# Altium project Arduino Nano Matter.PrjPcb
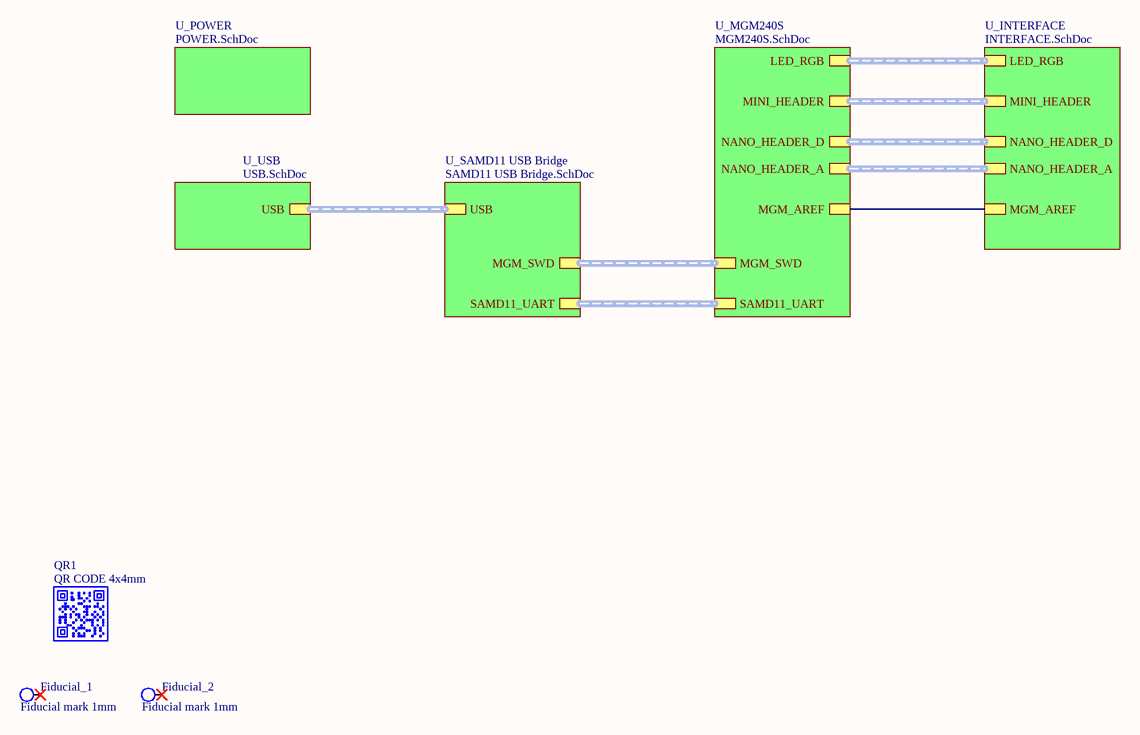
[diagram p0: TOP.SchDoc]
ASSEMBLY_BGA: _; ASSEMBLY_PRESSFIT: _; ASSEMBLY_SMD: X; ASSEMBLY_THT: X; BOARD_CODENAME: NANO MATTER; BOARD_INFO_AUTHOR_REV: Silvio Navaretti; BOARD_INFO_Er: _; BOARD_INFO_FLEX: _; BOARD_INFO_FR4: X; BOARD_INFO_FR4_HTG: _; BOARD_INFO_IPC1: _; BOARD_INFO_IPC2: X; BOARD_INFO_IPC3: _; BOARD_INFO_IPC_NA: _; BOARD_INFO_NUMBER_OF_LAYERS: 4; BOARD_INFO_PCB_SIZE: 43.18mm x 17.78mm; BOARD_INFO_POLYMIDE: _; BOARD_INFO_RIGID: X; BOARD_INFO_RIGID/FLEX: _; BOARD_INFO_TBD: _; BOARD_INFO_THICKNESS: 1.6mm; DRILLS_BLIND: _; DRILLS_BURIED: _; DRILLS_COPPER_FILLING: _; DRILLS_FULL: X; DRILLS_LASER: _; DRILLS_PRESSFIT: _; DRILLS_RESIN_FILLING: _; DRILLS_SLOT: _; DRILLS_SOLDER_FILLING: X; FINISH_ADJUSTMENTS: _; FINISH_EDGE_PLATING: _; FINISH_ENIG: X; FINISH_HAL: _; FINISH_HAL_LF: _; FINISH_NI/AU: _; FINISH_SILK_BOTTOM: X; FINISH_SILK_COLOR: WHITE; FINISH_SILK_TOP: X; FINISH_SN/PB: _; FINISH_SOLDERMASK_BOTTOM: X; FINISH_SOLDERMASK_COLOR: BLUE; FINISH_SOLDERMASK_PEELABLE_BOTTOM: _; FINISH_SOLDERMASK_PEELABLE_COLOR: _; FINISH_SOLDERMASK_PEELABLE_TOP: _; FINISH_SOLDERMASK_TOP: X; FINISH_TABS: _; FINISH_TBD: _; INSULATION_MIN_INNER: 0.127mm; INSULATION_MIN_OUTER: 0.127mm; PANEL_MILLING: X; PANEL_NOT_REQUESTED: _; PANEL_NUMBER_OF_FIGURES: 28; PANEL_PROVIDED: X; PANEL_REQUESTED: _; PANEL_SCORING: X; PANEL_SIZE: 211mm x 180.46mm; PANEL_TABS: _; SKU: ABX00112; TRACK_MIN_WIDTH_INNER: 0.127mm; TRACK_MIN_WIDTH_OUTER: 0.127mm; Version: V0.5; VIA_1: _; VIA_1_HOLE_MM: _; VIA_1_PAD_MM: _; VIA_2: _; VIA_2_HOLE_MM: _; VIA_2_PAD_MM: _; VIA_3: _; VIA_3_HOLE_MM: _; VIA_3_PAD_MM: _; VIA_4: _; VIA_4_HOLE_MM: _; VIA_4_PAD_MM: _; VIA_5: _; VIA_5_HOLE_MM: _; VIA_5_PAD_MM: _; VIA_THROUGH: X; VIA_THROUGH_HOLE_MM: 0.2; VIA_THROUGH_PAD_MM: 0.4
6 sheets, 72 parts. Net scope: hierarchical (ports join the sheet entries above them; power ports are global).
Board files: PCB.PcbDoc, PANEL.PcbDoc
Sheets:
  TOP.SchDoc
    U_SAMD11 USB Bridge = SAMD11 USB Bridge.SchDoc
    U_USB = USB.SchDoc
    U_POWER = POWER.SchDoc
    U_MGM240S = MGM240S.SchDoc
    U_INTERFACE = INTERFACE.SchDoc

## Sheet TOP.SchDoc: TOP
size A4; SheetNumber: 1; SheetTotal: 6

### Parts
Fiducial_1  Fiducial mark 1mm  [Fiducial mark 1mm-Footprint-1]  (no BOM)
Fiducial_2  Fiducial mark 1mm  [Fiducial mark 1mm-Footprint-1]  (no BOM)
QR1  QR CODE 4x4mm  [QR CODE 4x4mm]  (no BOM)

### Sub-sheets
U_INTERFACE = INTERFACE.SchDoc: LED_RGB (harness LED RGB), MINI_HEADER (harness 10P MINI HEADER), NANO_HEADER_D (harness NANO_HEADER_D), NANO_HEADER_A (harness NANO_HEADER_A), MGM_AREF
U_MGM240S = MGM240S.SchDoc: LED_RGB (harness LED RGB), MINI_HEADER (harness 10P MINI HEADER), NANO_HEADER_D (harness NANO_HEADER_D), NANO_HEADER_A (harness NANO_HEADER_A), MGM_SWD (harness UART), SAMD11_UART (harness UART), MGM_AREF
U_POWER = POWER.SchDoc: no entries
U_SAMD11 USB Bridge = SAMD11 USB Bridge.SchDoc: USB (harness USB), SAMD11_UART (harness SAMD11_UART), MGM_SWD (harness MGM_SW)
U_USB = USB.SchDoc: USB (harness USB)

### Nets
MGM_AREF: sheet U_MGM240S/MGM_AREF, sheet U_INTERFACE/MGM_AREF

Not connected (* = marked no-connect by the designer): Fiducial_1 1*; Fiducial_2 1*

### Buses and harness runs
harness sheet U_INTERFACE/LED_RGB = sheet U_MGM240S/LED_RGB
harness sheet U_INTERFACE/MINI_HEADER = sheet U_MGM240S/MINI_HEADER
harness sheet U_INTERFACE/NANO_HEADER_A = sheet U_MGM240S/NANO_HEADER_A
harness sheet U_INTERFACE/NANO_HEADER_D = sheet U_MGM240S/NANO_HEADER_D
harness sheet U_MGM240S/MGM_SWD = sheet U_SAMD11 USB Bridge/MGM_SWD
harness sheet U_MGM240S/SAMD11_UART = sheet U_SAMD11 USB Bridge/SAMD11_UART
harness sheet U_SAMD11 USB Bridge/USB = sheet U_USB/USB

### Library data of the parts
Fiducial_1 Fiducial_2 = UT0023-A.7: Fiducial mark 1mm clearance 2mm
QR1 = QR-0001-A.2: QR CODE 4x4mm on layer 34 (This is not a component); Code Arduino: QRCODE_4x4mm

## Sheet SAMD11 USB Bridge.SchDoc: SAMD11 BRIDGE
size A4; SheetNumber: 4; SheetTotal: 6
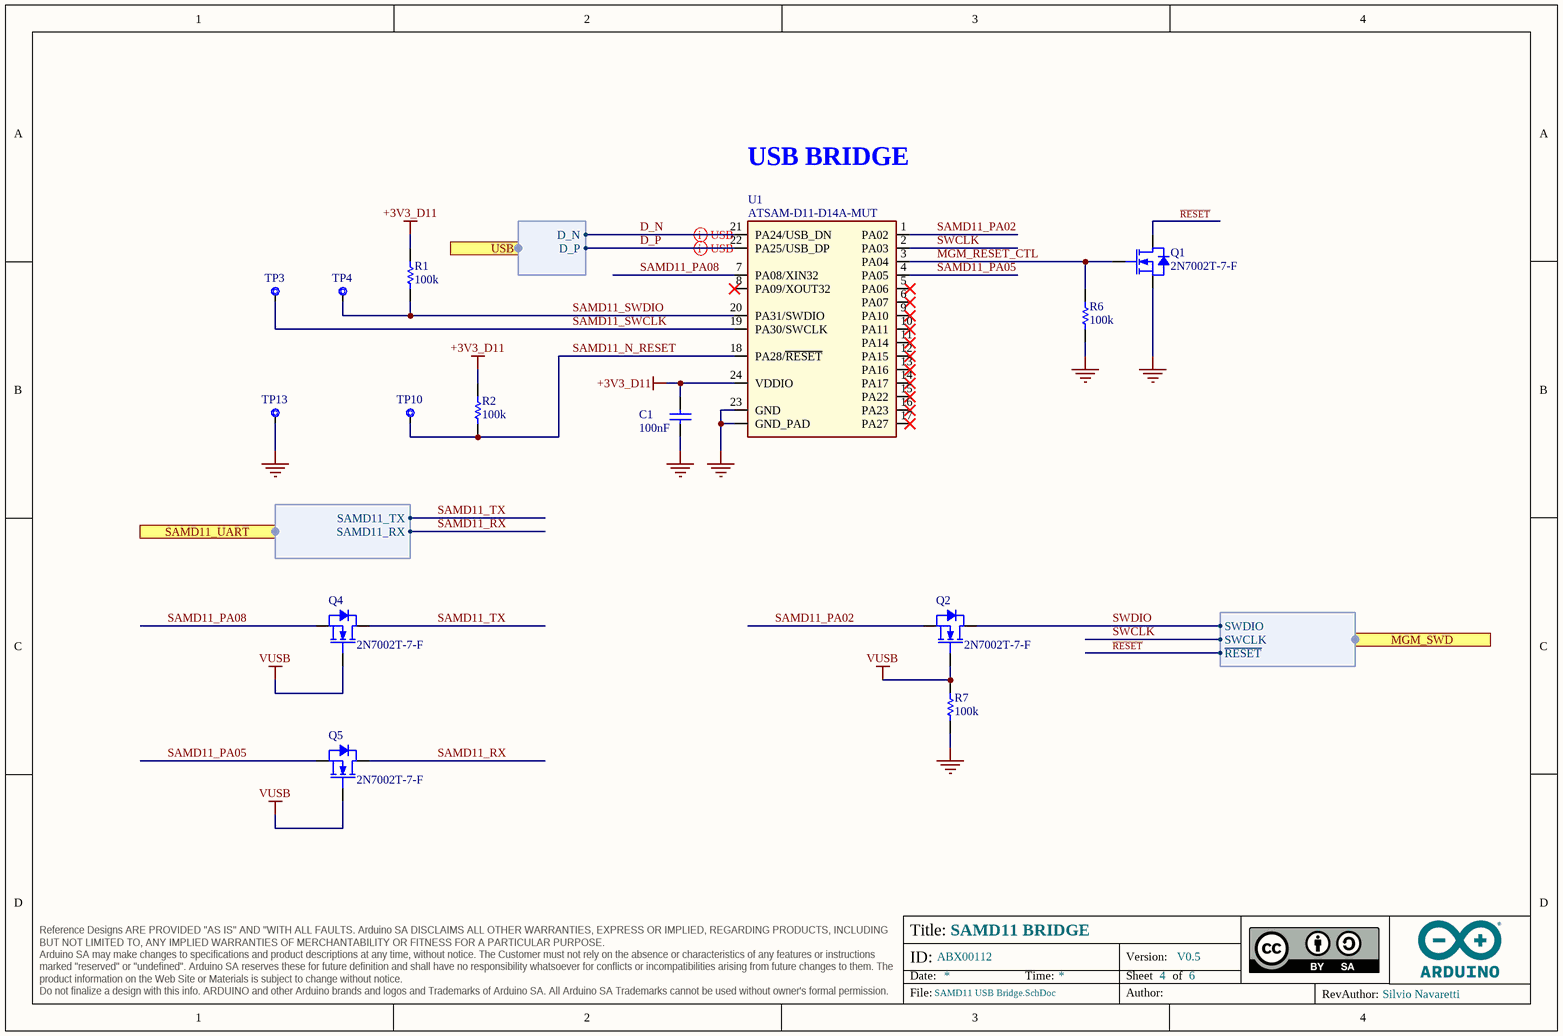
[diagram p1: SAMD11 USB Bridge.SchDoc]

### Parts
C1  value 100nF  [CAP-0201]  (hidden comment: CL03A104KP3NNNC)
Q1  2N7002T-7-F  [SOT523]
Q2  2N7002T-7-F  [SOT523]
Q4  2N7002T-7-F  [SOT523]
Q5  2N7002T-7-F  [SOT523]
R1  value 100k  [RES-0201]  (hidden comment: RC0201FR-07100KL)
R2  value 100k  [RES-0201]  (hidden comment: RC0201FR-07100KL)
R6  value 100k  [RES-0201]  (hidden comment: RC0201FR-07100KL)
R7  value 100k  [RES-0201]  (hidden comment: RC0201FR-07100KL)
TP3  Test point 1.00mm  [TP-1.00MM]  (value not drawn)  (no BOM)
TP4  Test point 1.00mm  [TP-1.00MM]  (value not drawn)  (no BOM)
TP10  Test point 1.00mm  [TP-1.00MM]  (value not drawn)  (no BOM)
TP13  Test point 1.00mm  [TP-1.00MM]  (value not drawn)  (no BOM)
U1  ATSAM-D11-D14A-MUT  [VQFN24]

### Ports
MGM_SWD (harness MGM_SWD), SAMD11_UART (harness SAMD11_UART), USB (out, harness USB)

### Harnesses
USB: D_P, D_N
SAMD11_UART: SAMD11_RX, SAMD11_TX
MGM_SWD: SWDIO, SWCLK, ~{RESET}

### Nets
+3V3_D11: C1.2 R1.2 R2.1 U1.24(VDDIO)
GND: C1.1 Q1.S R6.2 R7.2 TP13.X U1.23(GND) U1.EXP(GND_PAD)
VUSB: Q2.G Q4.G Q5.G R7.1
D_N: U1.21(PA24/USB_DN) ; port USB.D_N
D_P: U1.22(PA25/USB_DP) ; port USB.D_P
MGM_RESET_CTL: Q1.G R6.1 U1.3(PA04)  [project net MGM_RESET_CTL_4]
~{RESET}: Q1.D ; port MGM_SWD.~{RESET}
SAMD11_N_RESET: R2.2 TP10.X U1.18(PA28/~{RESET})  [project net SAMD11_N_RESET_4]
SAMD11_PA02: Q2.S U1.1(PA02)  [project net SAMD11_PA02_4]
SAMD11_PA05: Q5.S U1.4(PA05)  [project net SAMD11_PA05_4]
SAMD11_PA08: Q4.S U1.7(PA08/XIN32)  [project net SAMD11_PA08_4]
SAMD11_RX: Q5.D ; port SAMD11_UART.SAMD11_RX
SAMD11_SWCLK: TP3.X U1.19(PA30/SWCLK)  [project net SAMD11_SWCLK_4]
SAMD11_SWDIO: R1.1 TP4.X U1.20(PA31/SWDIO)  [project net SAMD11_SWDIO_4]
SAMD11_TX: Q4.D ; port SAMD11_UART.SAMD11_TX
SWCLK: U1.2(PA03) ; port MGM_SWD.SWCLK
SWDIO: Q2.D ; port MGM_SWD.SWDIO

Not connected (* = marked no-connect by the designer): U1 5(PA06)* 6(PA07)* 8(PA09/XOUT32)* 9(PA10)* 10(PA11)* 11(PA14)* 12(PA15)* 13(PA16)* 14(PA17)* 15(PA22)* 16(PA23)* 17(PA27)*

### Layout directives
differential pair; differential pair class USB: D_N, D_P

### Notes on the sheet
- USB BRIDGE

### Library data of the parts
C1 = C0113-A.6: CAP CHIP 0201 100nF 10% 10V X5R; Manufacturer: Samsung Electro-Mechanics; Code Arduino: C0113
Q1 Q2 Q4 Q5 = T0003-A.2: MOSFET N-CH 60V 115mA SOT523; Manufacturer: Diodes Inc.; Device Type: Mosfet N-CH SMD; Code Arduino: 2368
R1 R2 R6 R7 = R0146-A.21: RES CHIP 0201 100k 1% 1/20W; Manufacturer: Yageo; Power: 50mW; Code Arduino: R0146; Temperature coefficient: 200ppm
TP3 TP4 TP10 TP13 = UT0013-A.6: Manufacturer: This is not a component
U1 = U0040-A.9: IC uC Cortex M0, 16KB flash, 4KB SRAM, 48MHz, USB, 3x SERCOM, RTC, 12PWM, ADC 12b, DAC 10b, VDD 1.6V to 3.6V, QFN24 4x4mm; Manufacturer: Microchip

## Sheet USB.SchDoc: USB
size A4; SheetNumber: 3; SheetTotal: 6
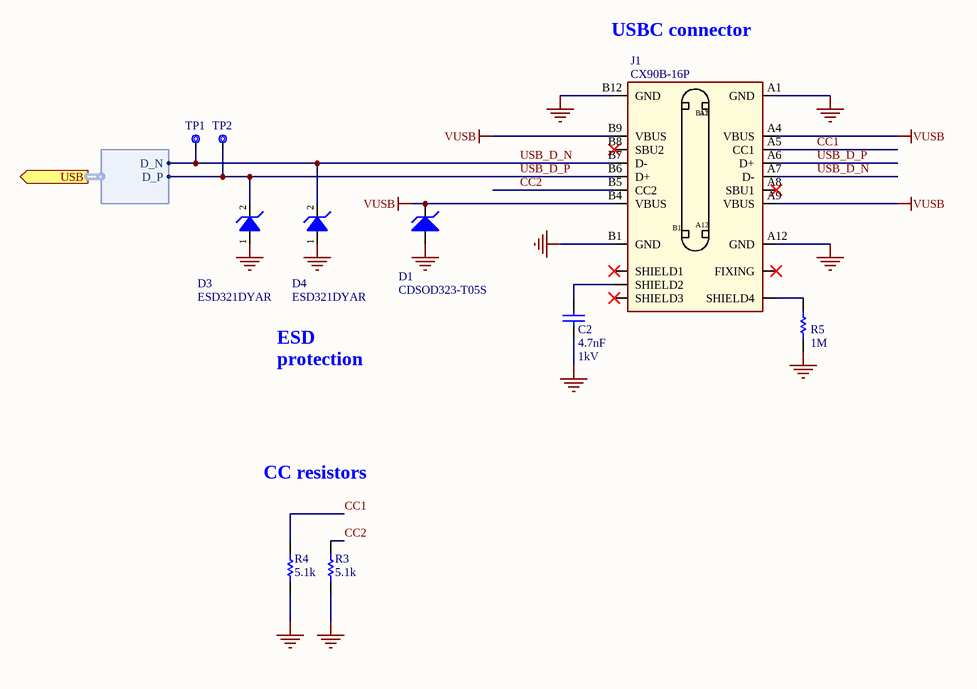
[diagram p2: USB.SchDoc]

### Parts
C2  value 4.7nF  Voltage: 1kV  [CAP-0805]  (hidden comment: FV21X472K102ECG)
D1  CDSOD323-T05S  [SOD323 CATHODE MARK]
D3  ESD321DYAR  [ESD321DYAR]
D4  ESD321DYAR  [ESD321DYAR]
J1  CX90B-16P  [CX90B-16P-Footprint-1]
R3  value 5.1k  [RES-0201]  (hidden comment: RC0201FR-075K1L)
R4  value 5.1k  [RES-0201]  (hidden comment: RC0201FR-075K1L)
R5  value 1M  [RES-0402]  (hidden comment: CRCW04021M00FKED)
TP1  Test point 1.00mm  [TP-1.00MM]  (value not drawn)  (no BOM)
TP2  Test point 1.00mm  [TP-1.00MM]  (value not drawn)  (no BOM)

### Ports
USB (out, harness USB)

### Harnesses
USB: D_P, D_N

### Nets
GND: C2.1 D1.2(A) D3.1 D4.1 J1.A1(GND) J1.A12(GND) J1.B1(GND) J1.B12(GND) R3.1 R4.1 R5.1
VUSB: D1.1(C) J1.A4(VBUS) J1.A9(VBUS) J1.B4(VBUS) J1.B9(VBUS)
CC1: J1.A5(CC1) R4.2  [project net CC1_3]
CC2: J1.B5(CC2) R3.2  [project net CC2_3]
USB_D_N: D4.2 J1.A7(D-) J1.B7(D-) TP1.X ; port USB.D_N  [project net D_N]
USB_D_P: D3.2 J1.A6(D+) J1.B6(D+) TP2.X ; port USB.D_P  [project net D_P]
NetC2_2: C2.2 J1.SHIELD2
NetJ1_SHIELD4: J1.SHIELD4 R5.2

Not connected (* = marked no-connect by the designer): J1 A8(SBU1)* B8(SBU2)* FIXING* SHIELD1* SHIELD3*

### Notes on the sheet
- USBC connector
- ESD
  protection
- CC resistors

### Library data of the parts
C2 = C0059-A.14: CAP CHIP 0805 4.7nF 10% 1000V X7R; Manufacturer: PSA Shenzen; Code Arduino: 0689
D1 = D0081-A.1: DIODE TVS Vr 5V, Vbr min 6V, 500W, SOD323; Manufacturer: Bourns; Direction: Unidirectional; Code Arduino: D0081
D3 D4 = P0022-4: TVS 1CH, 30kV, USB 2.0 ETH 10/100/1000, 0-3.6V, 0.9pF, IEC61000-4-5 peak current 80A surge 40W 6A, DC breakdown min 4.5V, SOD523 1.6x0.8mm; Manufacturer: Texas Instruments; Code Arduino: P0022
J1 = J0272-A.3: CONN RCPT USB3.1 TYPEC 16POS SMD; Manufacturer: Hirose; Code Arduino: J0272
R3 R4 = R0169-A.24: RES CHIP 0201 5.1k 1% 1/20W; Manufacturer: Yageo; Power: 50mW; Code Arduino: R0169; Temperature coefficient: 200ppm
R5 = R0058-A.24: RES CHIP 0402 1M 1% 1/16W; Manufacturer: Vishay; Power: 62.5mW; Code Arduino: 0139; Temperature coefficient: 100ppm
TP1 TP2 = UT0013-A.6: Manufacturer: This is not a component

## Sheet POWER.SchDoc: POWER
size A4; SheetNumber: 2; SheetTotal: 6
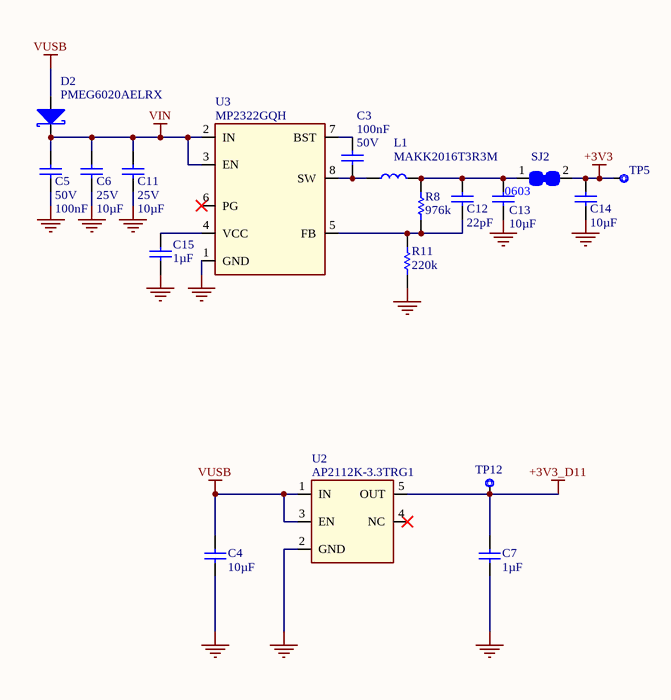
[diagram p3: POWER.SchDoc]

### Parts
C3  value 100nF  Voltage: 50V  [CAP-0402]  (hidden comment: GRM155R61H104KE19D)
C4  value 10µF  [CAP-0603]  (hidden comment: C1608A106M250NT)
C5  value 100nF  Voltage: 50V  [CAP-0402]  (hidden comment: GRM155R61H104KE19D)
C6  value 10µF  Voltage: 25V  [CAP-0603]  (hidden comment: C1608A106M250NT)
C7  value 1µF  [CAP-0201]  (hidden comment: GRM033R60J105MEA2D)
C11  value 10µF  Voltage: 25V  [CAP-0603]  (hidden comment: C1608A106M250NT)
C12  value 22pF  [CAP-0402]  (hidden comment: 0402N220J500CT)
C13  value 10µF  [CAP-0603]  (hidden comment: C1608A106M250NT)
C14  value 10µF  [CAP-0603]  (hidden comment: C1608A106M250NT)
C15  value 1µF  [CAP-0201]  (hidden comment: GRM033R60J105MEA2D)
D2  PMEG6020AELRX  [SOD123-1]
L1  MAKK2016T3R3M  [MAKK2016T3R3M-Footprint-1]
R8  value 976k  [RES-0201]  (hidden comment: RMCF0201FT976K)
R11  value 220k  [RES-0201]  (hidden comment: AC0201FR-07220KL)
SJ2  SOLDER JUMPER CLOSED 0603  [SJ 0603 CLOSED]  (value not drawn)  (no BOM)
TP5  Test point 1.00mm  [TP-1.00MM]  (value not drawn)  (no BOM)
TP12  Test point 1.00mm  [TP-1.00MM]  (value not drawn)  (no BOM)
U2  AP2112K-3.3TRG1  [SOT25]
U3  MP2322GQH  [QFN50P150X200X90-8L]

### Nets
+3V3: C14.2 SJ2.2 TP5.X
+3V3_D11: C7.2 TP12.X U2.5(OUT)
GND: C4.1 C5.2 C6.1 C7.1 C11.1 C13.1 C14.1 C15.1 R11.1 U2.2(GND) U3.1(GND)
VIN: C5.1 C6.2 C11.2 D2.C U3.2(IN) U3.3(EN)
VUSB: C4.2 D2.A U2.1(IN) U2.3(EN)
NetC3_1: C3.1 L1.1 U3.8(SW)
NetC3_2: C3.2 U3.7(BST)
NetC12_1: C12.1 R8.1 R11.2 U3.5(FB)
NetC12_2: C12.2 C13.2 L1.2 R8.2 SJ2.1
NetC15_2: C15.2 U3.4(VCC)

Not connected (* = marked no-connect by the designer): U2 4(NC)*; U3 6(PG)*

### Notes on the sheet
- BUCK 3V3
- LDO 3V3 DEDICATED TO D11

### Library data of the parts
C3 C5 = C0015-A.14: CAP CHIP 0402 100nF 10% 50V X5R; Manufacturer: Murata; Code Arduino: A5141
C4 C6 C11 C13 C14 = C0047-A.18: CAP CHIP 0603 10uF 20% 25V X5R; Manufacturer: Hottech; Code Arduino: 2213
C7 C15 = C0002-A.15: CAP CHIP 0201 1uF 20% 6.3V X5R; Manufacturer: Murata; Code Arduino: A5520
C12 = C0029-A.14: CAP CHIP 0402 22pF 5% 50V C0G; Manufacturer: Walsin; Code Arduino: 0137
D2 = D0026-A.6: DIODE SCHOTTKY SMD 2A 60V SOD123FL; Manufacturer: Nexperia; Manucturer Part Number 2: SS26L; Code Arduino: 2208; Forward Voltage: 0.6V; Manucturer 2: Hottech
L1 = I0045-A.10: IND CHIP 0806 3.3 uH 20% 1.2A; Manufacturer: Taiyo Yuden; Max DC Current: 1.15A; Core Material: Metal; DC Resistance (DCR): 255mR; Code Arduino: I0045; Test Frequency: 2MHz; Inductance: 3.3µH; Shielding: Shielded; Value: 3.3µH
R8 = R0198-A.20: RES CHIP 0201 976k 1% 1/20W; Manufacturer: Stackpole Electronics; Power: 50mW; Code Arduino: R0198; Temperature coefficient: 200ppm
R11 = R0199-A.20: RES CHIP 0201 220k 1% 1/20W; Manufacturer: Yageo; Code Arduino: R0199; Power: 50mW; Temperature coefficient: 200ppm
SJ2 = UT0039-A.3: Code Arduino: This is not a component
TP5 TP12 = UT0013-A.6: Manufacturer: This is not a component
U2 = U0027-A.11: IC LDO Vin max 6.5V Vout 3V3 Iout 600mA +EN  SOT25; Manufacturer: Diodes Inc; Code Arduino: 2199
U3 = U0072-A.8: IC STEP DOWN CONV 1A 22V QFN8; Manufacturer: Monolithic Power Systems; Code Arduino: U0072

## Sheet MGM240S.SchDoc: MGM240S
size A4; SheetNumber: 6; SheetTotal: 6
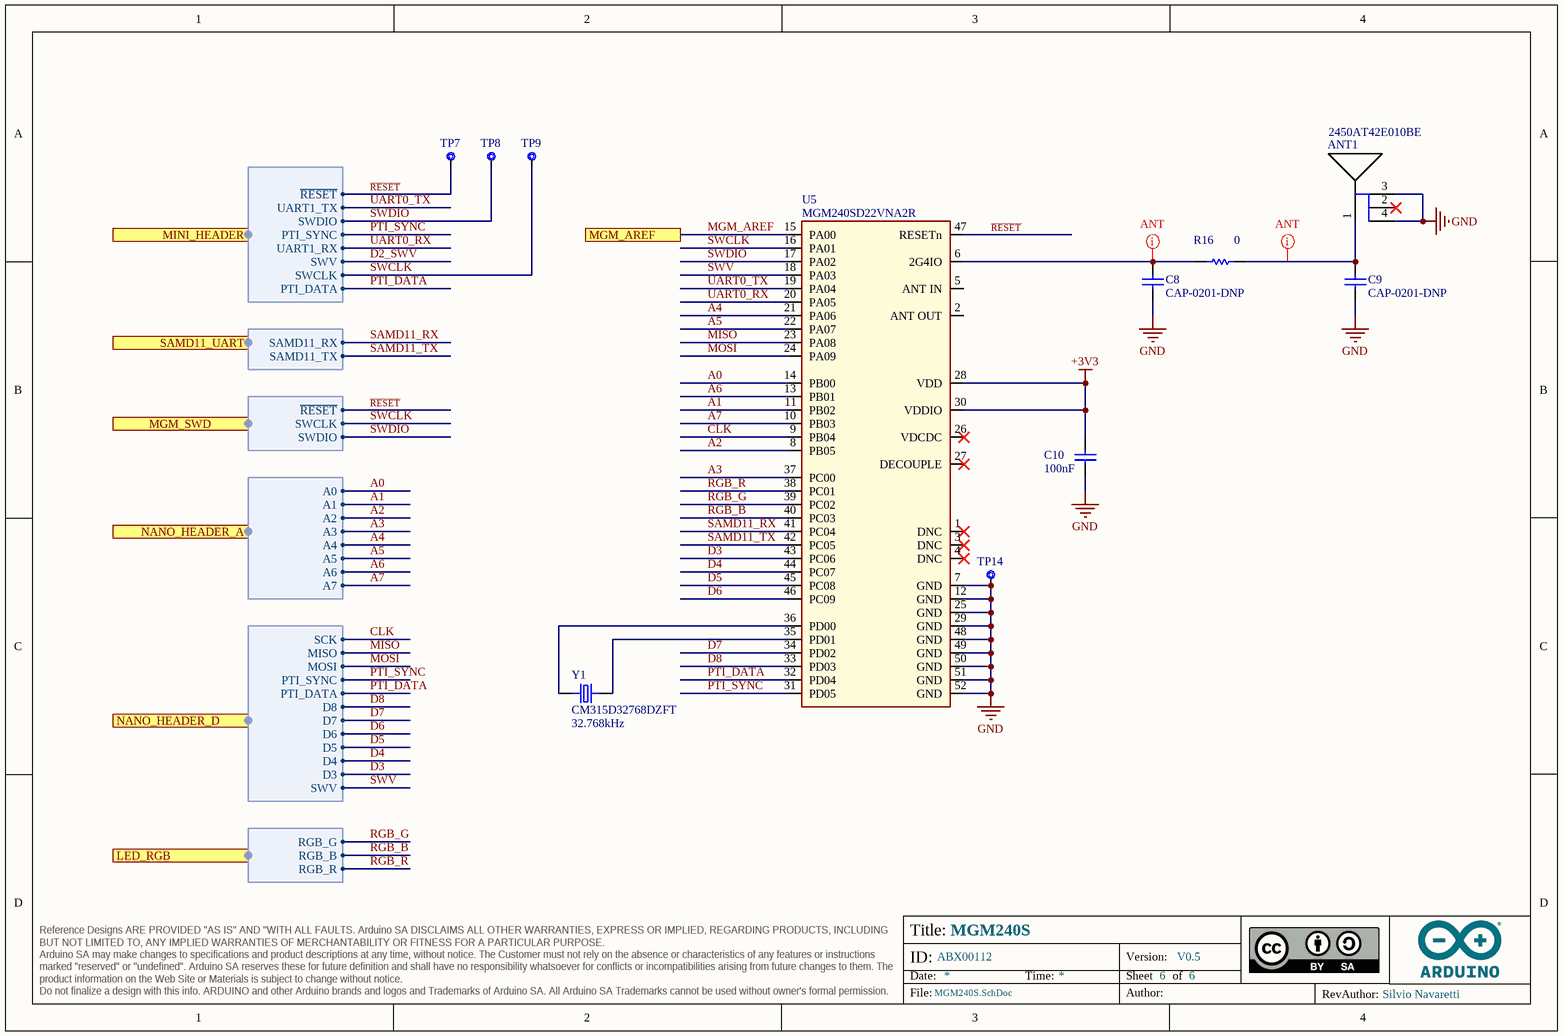
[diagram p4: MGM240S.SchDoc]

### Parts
ANT1  2450AT42E010BE  [2450AT42E0100E]
C8  CAP-0201-DNP  [CAP-0201]  (no BOM)
C9  CAP-0201-DNP  [CAP-0201]  (no BOM)
C10  value 100nF  [CAP-0201]  (hidden comment: CL03A104KP3NNNC)
R16  value 0  [RES-0201]  (hidden comment: CRCW02010000Z0ED)
TP7  Test point 1.00mm  [TP-1.00MM]  (value not drawn)  (no BOM)
TP8  Test point 1.00mm  [TP-1.00MM]  (value not drawn)  (no BOM)
TP9  Test point 1.00mm  [TP-1.00MM]  (value not drawn)  (no BOM)
TP14  Test point 1.00mm  [TP-1.00MM]  (value not drawn)  (no BOM)
U5  MGM240SD22VNA2R  [MGM240SD22VNA]
Y1  CM315D32768DZFT  Frequency: 32.768kHz  [ABS07]

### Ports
LED_RGB (harness LED RGB), MGM_AREF, MGM_SWD (harness MGM_SWD), MINI_HEADER (harness 10P MINI HEADER), NANO_HEADER_A (harness NANO_HEADER_A), NANO_HEADER_D (harness NANO_HEADER_D), SAMD11_UART (harness SAMD11_UART)

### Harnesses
10P MINI HEADER: SWDIO, UART1_TX, ~{RESET}, PTI_SYNC, UART1_RX, SWV, SWCLK, PTI_DATA
NANO_HEADER_D: SWV, D3, D4, D5, D6, D7, D8, PTI_DATA, PTI_SYNC, SCK, MISO, MOSI
NANO_HEADER_A: A0, A1, A2, A3, A4, A5, A6, A7
LED RGB: RGB_G, RGB_B, RGB_R
MGM_SWD: SWDIO, SWCLK, ~{RESET}
SAMD11_UART: SAMD11_RX, SAMD11_TX

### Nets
+3V3: C10.2 U5.28(VDD) U5.30(VDDIO)
GND: ANT1.3 ANT1.4 C8.2 C9.2 C10.1 TP14.X U5.7(GND) U5.12(GND) U5.25(GND) U5.29(GND) U5.48(GND) U5.49(GND) U5.50(GND) U5.51(GND) U5.52(GND)
A0: U5.14(PB00) ; port NANO_HEADER_A.A0
A1: U5.11(PB02) ; port NANO_HEADER_A.A1
A2: U5.8(PB05) ; port NANO_HEADER_A.A2
A3: U5.37(PC00) ; port NANO_HEADER_A.A3
A4: U5.21(PA06) ; port NANO_HEADER_A.A4
A5: U5.22(PA07) ; port NANO_HEADER_A.A5
A6: U5.13(PB01) ; port NANO_HEADER_A.A6
A7: U5.10(PB03) ; port NANO_HEADER_A.A7
CLK: U5.9(PB04) ; port NANO_HEADER_D.SCK
D2_SWV: U5.18(PA03) ; port MINI_HEADER.SWV, port NANO_HEADER_D.SWV  [also labelled SWV]
D3: U5.43(PC06) ; port NANO_HEADER_D.D3
D4: U5.44(PC07) ; port NANO_HEADER_D.D4
D5: U5.45(PC08) ; port NANO_HEADER_D.D5
D6: U5.46(PC09) ; port NANO_HEADER_D.D6
D7: U5.34(PD02) ; port NANO_HEADER_D.D7
D8: U5.33(PD03) ; port NANO_HEADER_D.D8
MGM_AREF: U5.15(PA00) ; port MGM_AREF
MISO: U5.23(PA08) ; port NANO_HEADER_D.MISO
MOSI: U5.24(PA09) ; port NANO_HEADER_D.MOSI
PTI_DATA: U5.32(PD04) ; port MINI_HEADER.PTI_DATA, port NANO_HEADER_D.PTI_DATA
PTI_SYNC: U5.31(PD05) ; port MINI_HEADER.PTI_SYNC, port NANO_HEADER_D.PTI_SYNC
~{RESET}: TP7.X U5.47(RESETn) ; port MINI_HEADER.~{RESET}, port MGM_SWD.~{RESET}
RGB_B: U5.40(PC03) ; port LED_RGB.RGB_B
RGB_G: U5.39(PC02) ; port LED_RGB.RGB_G
RGB_R: U5.38(PC01) ; port LED_RGB.RGB_R
SAMD11_RX: U5.41(PC04) ; port SAMD11_UART.SAMD11_RX
SAMD11_TX: U5.42(PC05) ; port SAMD11_UART.SAMD11_TX
SWCLK: TP9.X U5.16(PA01) ; port MINI_HEADER.SWCLK, port MGM_SWD.SWCLK
SWDIO: TP8.X U5.17(PA02) ; port MINI_HEADER.SWDIO, port MGM_SWD.SWDIO
UART0_RX: U5.20(PA05) ; port MINI_HEADER.UART1_RX
UART0_TX: U5.19(PA04) ; port MINI_HEADER.UART1_TX
NetANT1_1: ANT1.1 C9.1 R16.2
NetC8_1: C8.1 R16.1 U5.6(2G4IO)
NetU5_35: U5.35(PD01) Y1.2
NetU5_36: U5.36(PD00) Y1.1

Not connected (* = marked no-connect by the designer): ANT1 2*; U5 1(DNC)* 2(ANT_OUT) 3(DNC)* 4(DNC)* 5(ANT_IN) 26(VDCDC)* 27(DECOUPLE)*

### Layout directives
net class ANT: NetANT1_1, NetC8_1

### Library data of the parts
ANT1 = Y0004-A.2: ANTENNA CHIP 2.4GHZ; Manufacturer: Johanson; Code Arduino: Y0004; Number of Bands: 1; Max Frequency: 2.48GHz; Max Power Dissipation: 2W
C8 C9 = UT0015-A.7: DNP CAP CHIP 0201
C10 = C0113-A.6: as C1 on sheet SAMD11 USB Bridge
R16 = R0140-A.21: RES CHIP 0201 0R; Manufacturer: Vishay; Temperature coefficient: 0ppm; Code Arduino: R0140; Power: 50mW; Tolerance: 0%
TP7-TP9 TP14 = UT0013-A.6: Manufacturer: This is not a component
U5 = U0354-A.5: 802.15.4, Bluetooth Bluetooth v5.3, Thread, Zigbee® Transceiver Module 2.4GHz PCB Trace, Antenna Not Included, U.FL Surface Mount; Manufacturer: Silicon Labs; Code Arduino: U0354
Y1 = X0003-A.5: CRYSTAL 32.768kHz 20ppm 12.5pF SMD 1.6x0.9mm; Manufacturer: Citizen FineDevice; Series Resistance: 70kR; Code Arduino: 0213; Frequency Stability: 0.12%

## Sheet INTERFACE.SchDoc: INTERFACE
size A4; SheetNumber: 5; SheetTotal: 6
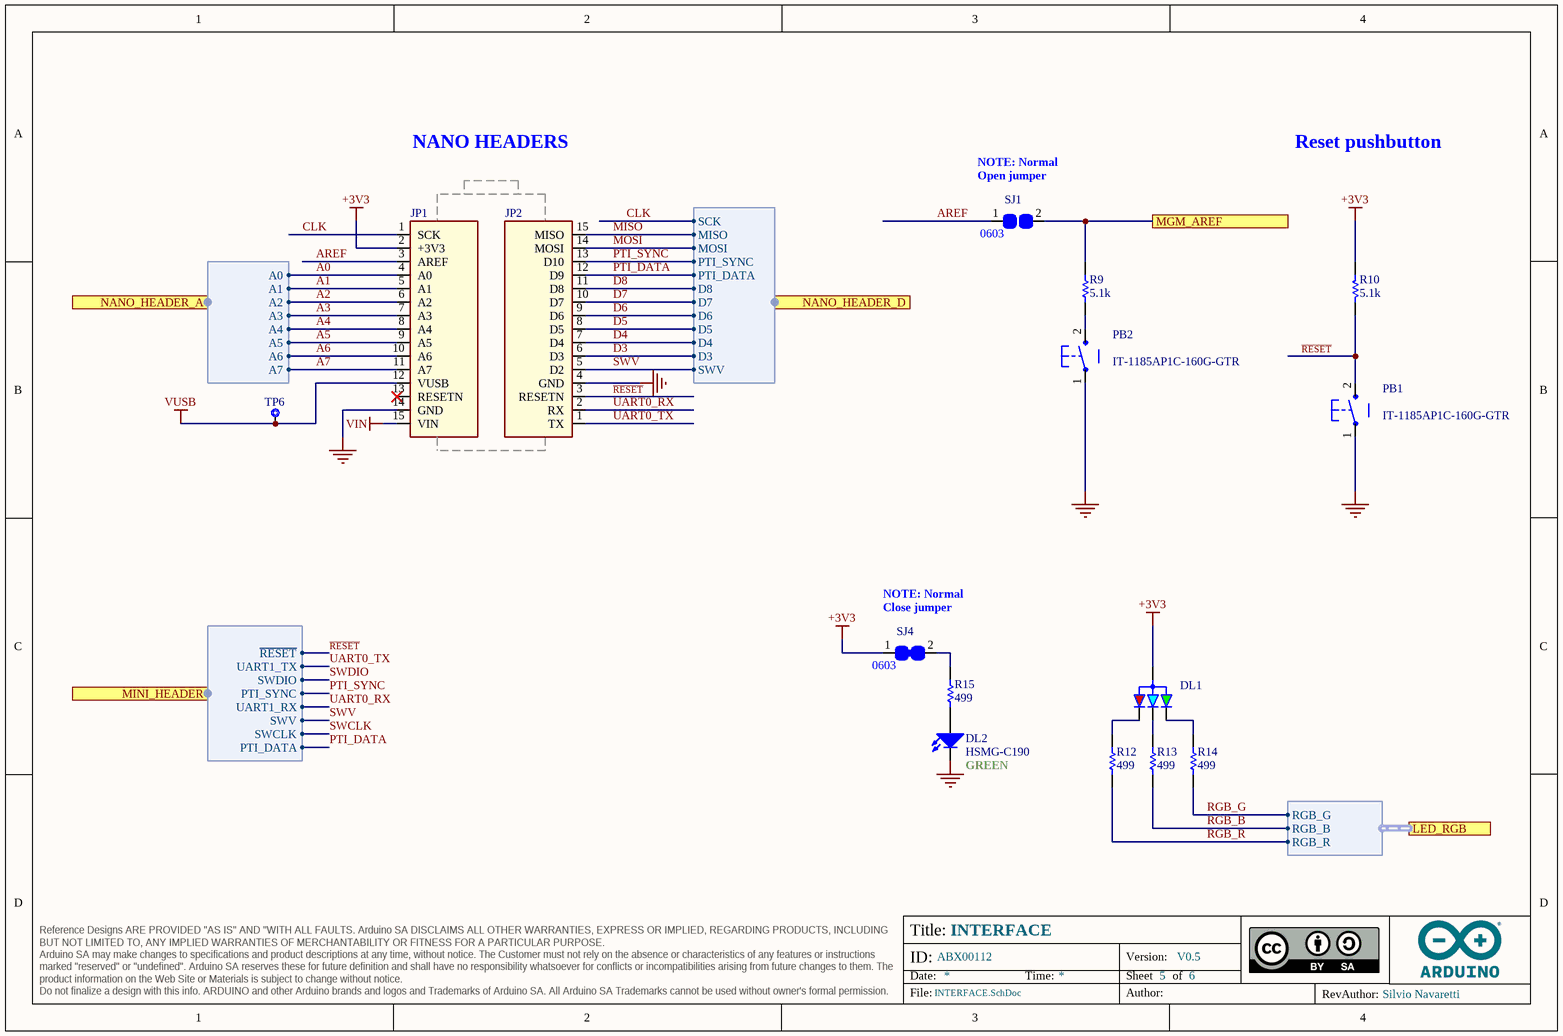
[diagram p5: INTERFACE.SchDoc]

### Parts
DL1  UHD1110-FKA-CL1A13R3Q1BBQFMF3  [UHD1110-FKA-CL1A13R3Q1BBQFMF3]  (value not drawn)
DL2  HSMG-C190  [LEDC1608X80N-AK]
JP1  PINHD-1X15-NANO-ANALOG-CASTELLATED  [PINHD-1X14_5VF]  (value not drawn)
JP2  PINHD-1X15-NANO-DIGITAL-CASTELLATED  [PINHD-1X14_5VF]  (value not drawn)
PB1  IT-1185AP1C-160G-GTR  [C&K_PTS820_NO_HOLES-1]
PB2  IT-1185AP1C-160G-GTR  [C&K_PTS820_NO_HOLES-1]
R9  value 5.1k  [RES-0201]  (hidden comment: RC0201FR-075K1L)
R10  value 5.1k  [RES-0201]  (hidden comment: RC0201FR-075K1L)
R12  value 499  [RES-0201]  (hidden comment: CRCW0201499RFKED)
R13  value 499  [RES-0201]  (hidden comment: CRCW0201499RFKED)
R14  value 499  [RES-0201]  (hidden comment: CRCW0201499RFKED)
R15  value 499  [RES-0201]  (hidden comment: CRCW0201499RFKED)
SJ1  SOLDER JUMPER OPEN 0603  [SJ]  (value not drawn)  (no BOM)
SJ4  SOLDER JUMPER CLOSED 0603  [SJ 0603 CLOSED]  (value not drawn)  (no BOM)
TP6  Test point 1.00mm  [TP-1.00MM]  (value not drawn)  (no BOM)

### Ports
LED_RGB (harness LED RGB), MGM_AREF, MINI_HEADER (harness 10P MINI HEADER), NANO_HEADER_A (harness NANO_HEADER_A), NANO_HEADER_D (harness NANO_HEADER_D)

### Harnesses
NANO_HEADER_D: MISO, MOSI, SWV, D3, D4, D5, D6, D7, D8, PTI_DATA, PTI_SYNC, SCK
LED RGB: RGB_G, RGB_B, RGB_R
10P MINI HEADER: SWDIO, UART1_TX, ~{RESET}, PTI_SYNC, UART1_RX, SWV, SWCLK, PTI_DATA
NANO_HEADER_A: A0, A1, A2, A3, A4, A5, A6, A7

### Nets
+3V3: DL1.4(ANODE) JP1.2(+3V3) R10.2 SJ4.1
GND: DL2.C JP1.14(GND) JP2.4(GND) PB1.1 PB2.1
VIN: JP1.15(VIN)
VUSB: JP1.12(VUSB) TP6.X
A0: JP1.4(A0) ; port NANO_HEADER_A.A0
A1: JP1.5(A1) ; port NANO_HEADER_A.A1
A2: JP1.6(A2) ; port NANO_HEADER_A.A2
A3: JP1.7(A3) ; port NANO_HEADER_A.A3
A4: JP1.8(A4) ; port NANO_HEADER_A.A4
A5: JP1.9(A5) ; port NANO_HEADER_A.A5
A6: JP1.10(A6) ; port NANO_HEADER_A.A6
A7: JP1.11(A7) ; port NANO_HEADER_A.A7
AREF: JP1.3(AREF) SJ1.1  [project net AREF_5]
CLK: JP1.1(SCK) ; port NANO_HEADER_D.SCK
D3: JP2.6(D3) ; port NANO_HEADER_D.D3
D4: JP2.7(D4) ; port NANO_HEADER_D.D4
D5: JP2.8(D5) ; port NANO_HEADER_D.D5
D6: JP2.9(D6) ; port NANO_HEADER_D.D6
D7: JP2.10(D7) ; port NANO_HEADER_D.D7
D8: JP2.11(D8) ; port NANO_HEADER_D.D8
MGM_AREF: R9.2 SJ1.2 ; port MGM_AREF
MISO: JP2.15(MISO) ; port NANO_HEADER_D.MISO
MOSI: JP2.14(MOSI) ; port NANO_HEADER_D.MOSI
PTI_DATA: JP2.12(D9) ; port NANO_HEADER_D.PTI_DATA, port MINI_HEADER.PTI_DATA
PTI_SYNC: JP2.13(D10) ; port NANO_HEADER_D.PTI_SYNC, port MINI_HEADER.PTI_SYNC
~{RESET}: JP2.3(RESETN) PB1.2 R10.1 ; port MINI_HEADER.~{RESET}
RGB_B: R13.2 ; port LED_RGB.RGB_B
RGB_G: R14.2 ; port LED_RGB.RGB_G
RGB_R: R12.2 ; port LED_RGB.RGB_R
SWV: JP2.5(D2) ; port NANO_HEADER_D.SWV, port MINI_HEADER.SWV  [project net D2_SWV]
UART0_RX: JP2.2(RX) ; port MINI_HEADER.UART1_RX
UART0_TX: JP2.1(TX) ; port MINI_HEADER.UART1_TX
NetDL1_1: DL1.1(BLUE_C) R13.1
NetDL1_2: DL1.2(GREEN_C) R14.1
NetDL1_3: DL1.3(RED_C) R12.1
NetDL2_A: DL2.A R15.1
NetPB2_2: PB2.2 R9.1
NetR15_2: R15.2 SJ4.2

Not connected (* = marked no-connect by the designer): JP1 13(RESETN)*

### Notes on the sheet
- NANO HEADERS
- Reset pushbutton
- (near SJ1) NOTE: Normal Open jumper
- (near SJ4) NOTE: Normal Close jumper
- (near DL2) GREEN

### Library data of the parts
DL1 = L0026-A.4: LED RGB BLACK BODY SMD; Manufacturer: Cree LED; Code Arduino: L0026
DL2 = L0009-A.5: LED SMD 0603 GREEN/568 15mcd 120^; Manufacturer: Broadcom; Code Arduino: 2204
JP1 = J0158-A.4: CONN THD SOCKET F/1/D 15V JANALOG NANO-TYPE CASTELLATED; Code Arduino: 0646
JP2 = J0183-A.4: CONN THD SOCKET F/1/D 15V JDIGITAL NANO-TYPE CASTELLATED; Code Arduino: 0646
PB1 PB2 = B0001-A.7: PUSHBUTTON WHITE NO ANCHORS; Manufacturer: Switronic; Code Arduino: 0173
R9 = R0169-A.24: RES CHIP 0201 5.1k 1% 1/20W; Manufacturer: Yageo; Power: 50mW; Temperature coefficient: 200ppm; Code Arduino: R0169
R10 = R0169-A.24: RES CHIP 0201 5.1k 1% 1/20W; Manufacturer: Yageo; Code Arduino: R0169; Power: 50mW; Temperature coefficient: 200ppm
R12-R14 = R0185-A.22: RES CHIP 0201 499R 1% 1/20W; Manufacturer: Vishay; Code Arduino: R0185; Temperature coefficient: 100ppm; Power: 50mW
R15 = R0185-A.22: RES CHIP 0201 499R 1% 1/20W; Manufacturer: Vishay; Code Arduino: R0185; Power: 50mW; Temperature coefficient: 100ppm
SJ1 = UT0038-A.4: Code Arduino: This is not a component
SJ4 = UT0039-A.3: Code Arduino: This is not a component
TP6 = UT0013-A.6: Manufacturer: This is not a component

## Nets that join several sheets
+3V3: POWER (C14.2 SJ2.2 TP5.X), MGM240S (C10.2 U5.28 U5.30), INTERFACE (DL1.4 JP1.2 R10.2 SJ4.1)
+3V3_D11: SAMD11 USB Bridge (C1.2 R1.2 R2.1 U1.24), POWER (C7.2 TP12.X U2.5)
GND: SAMD11 USB Bridge (7 pins), USB (11 pins), POWER (11 pins), MGM240S (15 pins), INTERFACE (5 pins)
VIN: POWER (6 pins), INTERFACE (JP1.15)
VUSB: SAMD11 USB Bridge (Q2.G Q4.G Q5.G R7.1), USB (5 pins), POWER (C4.2 D2.A U2.1 U2.3), INTERFACE (JP1.12 TP6.X)
A0: MGM240S (U5.14), INTERFACE (JP1.4)
A1: MGM240S (U5.11), INTERFACE (JP1.5)
A2: MGM240S (U5.8), INTERFACE (JP1.6)
A3: MGM240S (U5.37), INTERFACE (JP1.7)
A4: MGM240S (U5.21), INTERFACE (JP1.8)
A5: MGM240S (U5.22), INTERFACE (JP1.9)
A6: MGM240S (U5.13), INTERFACE (JP1.10)
A7: MGM240S (U5.10), INTERFACE (JP1.11)
CLK: MGM240S (U5.9), INTERFACE (JP1.1)
D2_SWV: MGM240S (U5.18), INTERFACE (JP2.5)
D3: MGM240S (U5.43), INTERFACE (JP2.6)
D4: MGM240S (U5.44), INTERFACE (JP2.7)
D5: MGM240S (U5.45), INTERFACE (JP2.8)
D6: MGM240S (U5.46), INTERFACE (JP2.9)
D7: MGM240S (U5.34), INTERFACE (JP2.10)
D8: MGM240S (U5.33), INTERFACE (JP2.11)
D_N: SAMD11 USB Bridge (U1.21), USB (D4.2 J1.A7 J1.B7 TP1.X)
D_P: SAMD11 USB Bridge (U1.22), USB (D3.2 J1.A6 J1.B6 TP2.X)
MGM_AREF: MGM240S (U5.15), INTERFACE (R9.2 SJ1.2)
MISO: MGM240S (U5.23), INTERFACE (JP2.15)
MOSI: MGM240S (U5.24), INTERFACE (JP2.14)
PTI_DATA: MGM240S (U5.32), INTERFACE (JP2.12)
PTI_SYNC: MGM240S (U5.31), INTERFACE (JP2.13)
~{RESET}: SAMD11 USB Bridge (Q1.D), MGM240S (TP7.X U5.47), INTERFACE (JP2.3 PB1.2 R10.1)
RGB_B: MGM240S (U5.40), INTERFACE (R13.2)
RGB_G: MGM240S (U5.39), INTERFACE (R14.2)
RGB_R: MGM240S (U5.38), INTERFACE (R12.2)
SAMD11_RX: SAMD11 USB Bridge (Q5.D), MGM240S (U5.41)
SAMD11_TX: SAMD11 USB Bridge (Q4.D), MGM240S (U5.42)
SWCLK: SAMD11 USB Bridge (U1.2), MGM240S (TP9.X U5.16)
SWDIO: SAMD11 USB Bridge (Q2.D), MGM240S (TP8.X U5.17)
UART0_RX: MGM240S (U5.20), INTERFACE (JP2.2)
UART0_TX: MGM240S (U5.19), INTERFACE (JP2.1)

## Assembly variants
ABX00112: not fitted C8 C9 JP1 JP2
